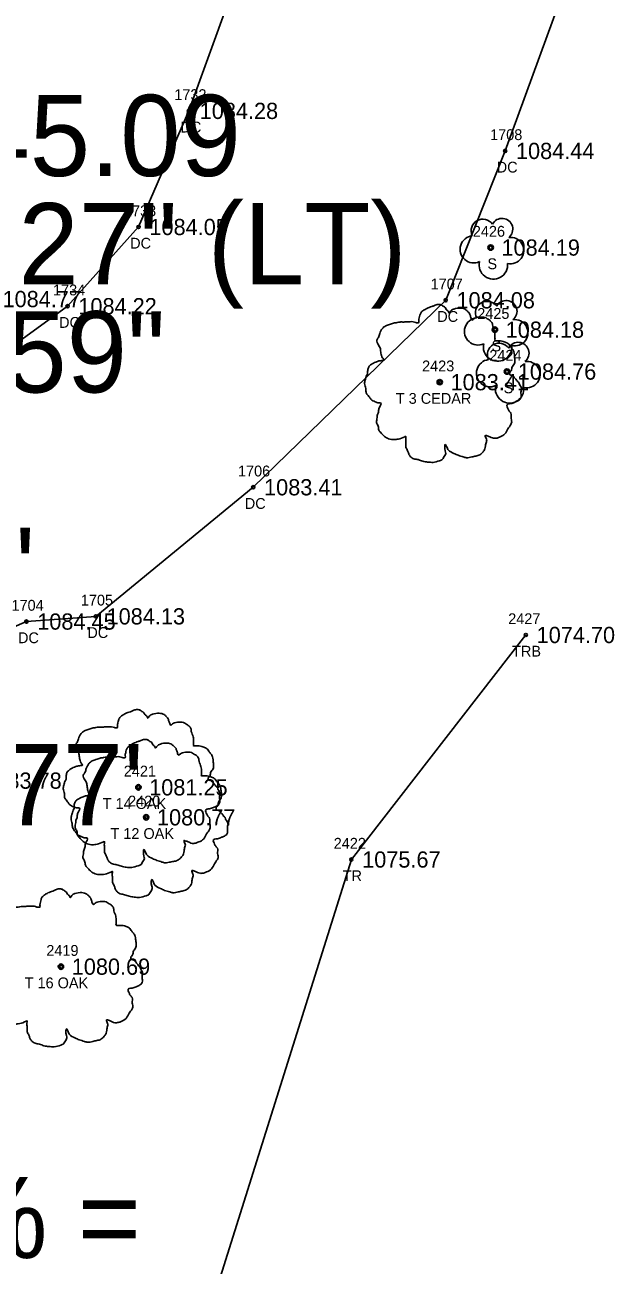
# Model space of a CAD drawing. Extents: x 1578957 to 1581675, y 1115963 to 1120391.
# Drawn here: x 1580765.6 to 1580820.1, y 1119196.4 to 1119311 of the extents above; entities that cross this region are included whole.
import ezdxf

# ---------------------------------------------------------------- set-up
doc = ezdxf.new("R2010")
doc.units = 0
for name, color, linetype in [('RD_EX_Conc', 7, 'Continuous'), ('RD_EX_Conc_txCode', 7, 'Continuous'), ('RD_EX_TX_Conc_ELEV', 7, 'Continuous'), ('RD_EX_TX_DV_Prop_ELEV', 7, 'Continuous'), ('RD_EX_TX_VEG_ELEV', 7, 'Continuous'), ('RD_EX_VEG', 7, 'Continuous'), ('RD_EX_VEG_txCode', 7, 'Continuous'), ('RD_HC_Data', 7, 'Continuous'), ('RD_SMD_Locator', 7, 'Continuous')]:
    doc.layers.add(name, color=color, linetype=linetype)

msp = doc.modelspace()

# ---------------------------------------------------------------- linework, layer by layer
at = {"layer": 'RD_EX_Conc'}
for points in [[(1580798.47, 1119328.92), (1580798.7, 1119324.38), (1580789.8, 1119327.91), (1580780.78, 1119303.02), (1580776.13, 1119292.29), (1580769.56, 1119284.97), (1580747.89, 1119269.22), (1580734.35, 1119264.63), (1580723.65, 1119263.02), (1580716.19, 1119263.31), (1580710.46, 1119268.63)], [(1580700.9, 1119243.15), (1580707.94, 1119242.34), (1580725.73, 1119233.32), (1580737.41, 1119227.45), (1580747.39, 1119244.58), (1580757.33, 1119252.19), (1580765.76, 1119255.83), (1580772.17, 1119256.31), (1580786.73, 1119268.24), (1580804.52, 1119285.52), (1580810.02, 1119299.32), (1580818.24, 1119321.88)]]:
    msp.add_lwpolyline(points, dxfattribs=at)
at = {"layer": 'RD_EX_VEG'}
msp.add_lwpolyline([(1580738.38, 1119110.04), (1580691.44, 1119109.82), (1580661.65, 1119118.46), (1580716.03, 1119209.67), (1580734.07, 1119204.79), (1580780.32, 1119184.53), (1580795.8, 1119233.84), (1580811.93, 1119254.59)], dxfattribs=at)
for centre, radius in [((1580808.68, 1119290.39), 0.25), ((1580809.07, 1119282.8), 0.25), ((1580803.97, 1119277.95), 0.25), ((1580810.19, 1119278.93), 0.25), ((1580803.96, 1119277.93), 0.0001), ((1580776.11, 1119240.51), 0.25), ((1580776.1, 1119240.49), 0.0001), ((1580776.83, 1119237.74), 0.25), ((1580776.82, 1119237.72), 0.0001), ((1580768.95, 1119223.94), 0.25), ((1580768.93, 1119223.92), 0.0001)]:
    msp.add_circle(centre, radius, dxfattribs=at)
for centre, radius, start, end in [((1580807.96, 1119291.94), 1.08, 34.9763, 204.756), ((1580809.73, 1119292.09), 0.995, 308.7626, 152.0467), ((1580807.12, 1119290.23), 1.26, 96.4518, 294.734), ((1580810.52, 1119290.11), 1.22, 256.5667, 98.1046), ((1580808.93, 1119288.79), 1.32, 166.8827, 5.7589), ((1580808.35, 1119284.34), 1.08, 34.9763, 204.756), ((1580810.12, 1119284.5), 0.995, 308.7626, 152.0467), ((1580807.51, 1119282.64), 1.26, 96.4518, 294.734), ((1580810.91, 1119282.52), 1.22, 256.5667, 98.1046), ((1580809.46, 1119280.48), 1.08, 34.9763, 204.756), ((1580811.23, 1119280.64), 0.995, 308.7626, 152.0467), ((1580809.32, 1119281.2), 1.32, 166.8827, 5.7589), ((1580808.62, 1119278.78), 1.26, 96.4518, 294.734), ((1580812.03, 1119278.65), 1.22, 256.5667, 98.1046), ((1580810.43, 1119277.34), 1.32, 166.8827, 5.7589)]:
    msp.add_arc(centre, radius, start, end, dxfattribs=at)
for points in [[(1580804.1, 1119285.11), (1580803.8, 1119285.14), (1580803.48, 1119285.04), (1580803.23, 1119284.94), (1580803, 1119284.86), (1580802.78, 1119284.76), (1580802.48, 1119284.59), (1580802.25, 1119284.39), (1580802.13, 1119284.14), (1580802.08, 1119283.91), (1580802.03, 1119283.64), (1580802.03, 1119283.46), (1580801.9, 1119283.44), (1580801.75, 1119283.46), (1580801.5, 1119283.54), (1580801.25, 1119283.54), (1580801, 1119283.54), (1580800.65, 1119283.51), (1580800.3, 1119283.51), (1580800.03, 1119283.46), (1580799.7, 1119283.41), (1580799.33, 1119283.29), (1580798.98, 1119283.16), (1580798.68, 1119282.91), (1580798.43, 1119282.44), (1580798.3, 1119282.09), (1580798.16, 1119281.84), (1580798.3, 1119281.39), (1580798.48, 1119281.04), (1580798.5, 1119280.84), (1580798.58, 1119280.41), (1580798.68, 1119280.19), (1580798.8, 1119279.99), (1580798.73, 1119279.96), (1580798.35, 1119279.91), (1580798.06, 1119279.81), (1580797.63, 1119279.59), (1580797.41, 1119279.36), (1580797.31, 1119279.04), (1580797.28, 1119278.69), (1580797.18, 1119278.49), (1580797.11, 1119278.22), (1580797.08, 1119278.14), (1580797.03, 1119277.82), (1580797.13, 1119277.37), (1580797.16, 1119277.02), (1580797.28, 1119276.79), (1580797.43, 1119276.62), (1580797.61, 1119276.37), (1580798.01, 1119276.14), (1580798.33, 1119276.04), (1580798.53, 1119276.02), (1580798.35, 1119275.52), (1580798.3, 1119275.17), (1580798.18, 1119274.77), (1580798.18, 1119274.69), (1580798.13, 1119274.22), (1580798.28, 1119273.89), (1580798.35, 1119273.52), (1580798.53, 1119273.29), (1580798.8, 1119272.99), (1580799.13, 1119272.77), (1580799.63, 1119272.64), (1580800.03, 1119272.67), (1580800.6, 1119272.84), (1580800.85, 1119272.92), (1580800.83, 1119272.74), (1580800.85, 1119272.37), (1580800.85, 1119271.94), (1580801, 1119271.62), (1580801.1, 1119271.34), (1580801.25, 1119271.09), (1580801.58, 1119270.87), (1580801.98, 1119270.79), (1580802.4, 1119270.64), (1580802.85, 1119270.57), (1580803.35, 1119270.54), (1580803.95, 1119270.69), (1580804.23, 1119270.82), (1580804.33, 1119270.99), (1580804.53, 1119271.37), (1580804.48, 1119271.59), (1580804.5, 1119272.19), (1580804.6, 1119272.02), (1580804.78, 1119271.67), (1580805.28, 1119271.37), (1580805.68, 1119271.19), (1580806.15, 1119271.04), (1580806.45, 1119270.97), (1580806.93, 1119271.04), (1580807.3, 1119271.12), (1580807.68, 1119271.24), (1580807.98, 1119271.52), (1580808.15, 1119271.79), (1580808.2, 1119272.07), (1580808.28, 1119272.44), (1580808.33, 1119272.62)], [(1580808.33, 1119272.62), (1580808.25, 1119272.79), (1580808.2, 1119273.04), (1580808.28, 1119273.02), (1580808.45, 1119272.97), (1580808.73, 1119272.84), (1580808.95, 1119272.77), (1580809.28, 1119272.79), (1580809.55, 1119272.89), (1580810, 1119273.17), (1580810.27, 1119273.64), (1580810.55, 1119274.04), (1580810.62, 1119274.37), (1580810.57, 1119274.59), (1580810.55, 1119275.09), (1580810.35, 1119275.34), (1580810.3, 1119275.47), (1580810.2, 1119275.87), (1580810.27, 1119275.92), (1580810.55, 1119275.97), (1580810.92, 1119276.09), (1580811.2, 1119276.22), (1580811.42, 1119276.39), (1580811.5, 1119276.62), (1580811.47, 1119277.02), (1580811.52, 1119277.42), (1580811.45, 1119277.57), (1580811.35, 1119277.72), (1580811.27, 1119277.92), (1580811.12, 1119278.07), (1580811.02, 1119278.22), (1580810.92, 1119278.32), (1580810.8, 1119278.47), (1580810.62, 1119278.59), (1580810.47, 1119278.64), (1580810.42, 1119278.79), (1580810.57, 1119278.99), (1580810.62, 1119279.09), (1580810.65, 1119279.31), (1580810.87, 1119279.66), (1580810.92, 1119280.06), (1580810.87, 1119280.49), (1580810.82, 1119280.76), (1580810.67, 1119281.04), (1580810.47, 1119281.29), (1580810.35, 1119281.46), (1580810.17, 1119281.59), (1580809.85, 1119281.71), (1580809.6, 1119281.76), (1580809.25, 1119281.76), (1580809.05, 1119281.81), (1580809.08, 1119281.86), (1580809.08, 1119282.01), (1580809.08, 1119282.29), (1580809, 1119282.74), (1580808.85, 1119283.24), (1580808.85, 1119283.26), (1580808.75, 1119283.51), (1580808.53, 1119283.71), (1580808.35, 1119283.81), (1580808.15, 1119283.94), (1580807.9, 1119283.96), (1580807.6, 1119283.96), (1580807.33, 1119283.91), (1580807.13, 1119283.81), (1580806.95, 1119283.69), (1580806.88, 1119283.84), (1580806.78, 1119284.14), (1580806.73, 1119284.29), (1580806.58, 1119284.46), (1580806.35, 1119284.66), (1580805.9, 1119284.79), (1580805.28, 1119284.71), (1580804.98, 1119284.51), (1580804.83, 1119284.34), (1580804.78, 1119284.46), (1580804.58, 1119284.66), (1580804.48, 1119284.84), (1580804.3, 1119284.96), (1580804.15, 1119285.06), (1580804.05, 1119285.11)], [(1580776.24, 1119247.68), (1580775.94, 1119247.7), (1580775.62, 1119247.6), (1580775.37, 1119247.5), (1580775.14, 1119247.43), (1580774.92, 1119247.33), (1580774.62, 1119247.15), (1580774.39, 1119246.95), (1580774.27, 1119246.7), (1580774.22, 1119246.48), (1580774.17, 1119246.2), (1580774.17, 1119246.03), (1580774.04, 1119246), (1580773.89, 1119246.03), (1580773.64, 1119246.1), (1580773.39, 1119246.1), (1580773.14, 1119246.1), (1580772.79, 1119246.08), (1580772.44, 1119246.08), (1580772.17, 1119246.03), (1580771.84, 1119245.98), (1580771.47, 1119245.85), (1580771.12, 1119245.73), (1580770.82, 1119245.48), (1580770.57, 1119245), (1580770.44, 1119244.65), (1580770.29, 1119244.4), (1580770.44, 1119243.95), (1580770.62, 1119243.6), (1580770.64, 1119243.4), (1580770.72, 1119242.98), (1580770.82, 1119242.75), (1580770.94, 1119242.55), (1580770.87, 1119242.53), (1580770.49, 1119242.48), (1580770.19, 1119242.38), (1580769.77, 1119242.15), (1580769.54, 1119241.93), (1580769.44, 1119241.6), (1580769.42, 1119241.25), (1580769.32, 1119241.05), (1580769.24, 1119240.78), (1580769.22, 1119240.7), (1580769.17, 1119240.38), (1580769.27, 1119239.93), (1580769.29, 1119239.58), (1580769.42, 1119239.36), (1580769.57, 1119239.18), (1580769.74, 1119238.93), (1580770.14, 1119238.71), (1580770.47, 1119238.61), (1580770.67, 1119238.58), (1580770.49, 1119238.08), (1580770.44, 1119237.73), (1580770.32, 1119237.33), (1580770.32, 1119237.26), (1580770.27, 1119236.78), (1580770.42, 1119236.46), (1580770.49, 1119236.08), (1580770.67, 1119235.86), (1580770.94, 1119235.56), (1580771.27, 1119235.33), (1580771.77, 1119235.21), (1580772.17, 1119235.23), (1580772.74, 1119235.41), (1580772.99, 1119235.48), (1580772.97, 1119235.31), (1580772.99, 1119234.93), (1580772.99, 1119234.51), (1580773.14, 1119234.18), (1580773.24, 1119233.91), (1580773.39, 1119233.66), (1580773.72, 1119233.43), (1580774.12, 1119233.36), (1580774.54, 1119233.21), (1580774.99, 1119233.13), (1580775.49, 1119233.11), (1580776.09, 1119233.26), (1580776.37, 1119233.38), (1580776.47, 1119233.56), (1580776.67, 1119233.93), (1580776.62, 1119234.16), (1580776.64, 1119234.76), (1580776.74, 1119234.58), (1580776.92, 1119234.23), (1580777.42, 1119233.93), (1580777.82, 1119233.76), (1580778.29, 1119233.61), (1580778.59, 1119233.53), (1580779.06, 1119233.61), (1580779.44, 1119233.68), (1580779.81, 1119233.81), (1580780.11, 1119234.08), (1580780.29, 1119234.36), (1580780.34, 1119234.63), (1580780.41, 1119235.01), (1580780.46, 1119235.18)], [(1580780.46, 1119235.18), (1580780.39, 1119235.36), (1580780.34, 1119235.61), (1580780.41, 1119235.58), (1580780.59, 1119235.53), (1580780.86, 1119235.41), (1580781.09, 1119235.33), (1580781.41, 1119235.36), (1580781.69, 1119235.46), (1580782.14, 1119235.73), (1580782.41, 1119236.21), (1580782.69, 1119236.61), (1580782.76, 1119236.93), (1580782.71, 1119237.16), (1580782.69, 1119237.66), (1580782.49, 1119237.91), (1580782.44, 1119238.03), (1580782.34, 1119238.43), (1580782.41, 1119238.48), (1580782.69, 1119238.53), (1580783.06, 1119238.66), (1580783.34, 1119238.78), (1580783.56, 1119238.96), (1580783.64, 1119239.18), (1580783.61, 1119239.58), (1580783.66, 1119239.98), (1580783.59, 1119240.13), (1580783.49, 1119240.28), (1580783.41, 1119240.48), (1580783.26, 1119240.63), (1580783.16, 1119240.78), (1580783.06, 1119240.88), (1580782.94, 1119241.03), (1580782.76, 1119241.15), (1580782.61, 1119241.2), (1580782.56, 1119241.35), (1580782.71, 1119241.55), (1580782.76, 1119241.65), (1580782.79, 1119241.88), (1580783.01, 1119242.23), (1580783.06, 1119242.63), (1580783.01, 1119243.05), (1580782.96, 1119243.33), (1580782.81, 1119243.6), (1580782.61, 1119243.85), (1580782.49, 1119244.03), (1580782.31, 1119244.15), (1580781.99, 1119244.28), (1580781.74, 1119244.33), (1580781.39, 1119244.33), (1580781.19, 1119244.38), (1580781.21, 1119244.43), (1580781.21, 1119244.58), (1580781.21, 1119244.85), (1580781.14, 1119245.3), (1580780.99, 1119245.8), (1580780.99, 1119245.83), (1580780.89, 1119246.08), (1580780.66, 1119246.28), (1580780.49, 1119246.38), (1580780.29, 1119246.5), (1580780.04, 1119246.53), (1580779.74, 1119246.53), (1580779.46, 1119246.48), (1580779.26, 1119246.38), (1580779.09, 1119246.25), (1580779.01, 1119246.4), (1580778.91, 1119246.7), (1580778.86, 1119246.85), (1580778.71, 1119247.03), (1580778.49, 1119247.23), (1580778.04, 1119247.35), (1580777.42, 1119247.28), (1580777.12, 1119247.08), (1580776.97, 1119246.9), (1580776.92, 1119247.03), (1580776.72, 1119247.23), (1580776.62, 1119247.4), (1580776.44, 1119247.53), (1580776.29, 1119247.63), (1580776.19, 1119247.68)], [(1580776.97, 1119244.91), (1580776.67, 1119244.94), (1580776.34, 1119244.84), (1580776.09, 1119244.74), (1580775.87, 1119244.66), (1580775.64, 1119244.56), (1580775.34, 1119244.39), (1580775.12, 1119244.19), (1580774.99, 1119243.94), (1580774.94, 1119243.71), (1580774.89, 1119243.44), (1580774.89, 1119243.26), (1580774.77, 1119243.24), (1580774.62, 1119243.26), (1580774.37, 1119243.34), (1580774.12, 1119243.34), (1580773.87, 1119243.34), (1580773.52, 1119243.31), (1580773.17, 1119243.31), (1580772.89, 1119243.26), (1580772.57, 1119243.21), (1580772.19, 1119243.09), (1580771.84, 1119242.96), (1580771.54, 1119242.71), (1580771.29, 1119242.24), (1580771.17, 1119241.89), (1580771.02, 1119241.64), (1580771.17, 1119241.19), (1580771.34, 1119240.84), (1580771.37, 1119240.64), (1580771.44, 1119240.21), (1580771.54, 1119239.99), (1580771.67, 1119239.79), (1580771.59, 1119239.76), (1580771.22, 1119239.71), (1580770.92, 1119239.61), (1580770.49, 1119239.39), (1580770.27, 1119239.16), (1580770.17, 1119238.84), (1580770.14, 1119238.49), (1580770.04, 1119238.29), (1580769.97, 1119238.01), (1580769.94, 1119237.94), (1580769.89, 1119237.61), (1580769.99, 1119237.16), (1580770.02, 1119236.81), (1580770.14, 1119236.59), (1580770.29, 1119236.41), (1580770.47, 1119236.16), (1580770.87, 1119235.94), (1580771.19, 1119235.84), (1580771.39, 1119235.81), (1580771.22, 1119235.31), (1580771.17, 1119234.96), (1580771.04, 1119234.57), (1580771.04, 1119234.49), (1580770.99, 1119234.02), (1580771.14, 1119233.69), (1580771.22, 1119233.32), (1580771.39, 1119233.09), (1580771.67, 1119232.79), (1580771.99, 1119232.57), (1580772.49, 1119232.44), (1580772.89, 1119232.47), (1580773.47, 1119232.64), (1580773.72, 1119232.72), (1580773.69, 1119232.54), (1580773.72, 1119232.17), (1580773.72, 1119231.74), (1580773.87, 1119231.42), (1580773.97, 1119231.14), (1580774.12, 1119230.89), (1580774.44, 1119230.67), (1580774.84, 1119230.59), (1580775.27, 1119230.44), (1580775.72, 1119230.37), (1580776.22, 1119230.34), (1580776.82, 1119230.49), (1580777.09, 1119230.62), (1580777.19, 1119230.79), (1580777.39, 1119231.17), (1580777.34, 1119231.39), (1580777.37, 1119231.99), (1580777.47, 1119231.82), (1580777.64, 1119231.47), (1580778.14, 1119231.17), (1580778.54, 1119230.99), (1580779.01, 1119230.84), (1580779.31, 1119230.77), (1580779.79, 1119230.84), (1580780.16, 1119230.92), (1580780.54, 1119231.04), (1580780.84, 1119231.32), (1580781.01, 1119231.59), (1580781.06, 1119231.87), (1580781.14, 1119232.24), (1580781.19, 1119232.42)], [(1580781.19, 1119232.42), (1580781.11, 1119232.59), (1580781.06, 1119232.84), (1580781.14, 1119232.82), (1580781.31, 1119232.77), (1580781.59, 1119232.64), (1580781.81, 1119232.57), (1580782.14, 1119232.59), (1580782.41, 1119232.69), (1580782.86, 1119232.97), (1580783.14, 1119233.44), (1580783.41, 1119233.84), (1580783.49, 1119234.17), (1580783.44, 1119234.39), (1580783.41, 1119234.89), (1580783.21, 1119235.14), (1580783.16, 1119235.26), (1580783.06, 1119235.66), (1580783.14, 1119235.71), (1580783.41, 1119235.76), (1580783.79, 1119235.89), (1580784.06, 1119236.01), (1580784.29, 1119236.19), (1580784.36, 1119236.41), (1580784.34, 1119236.81), (1580784.39, 1119237.21), (1580784.31, 1119237.36), (1580784.21, 1119237.51), (1580784.14, 1119237.71), (1580783.99, 1119237.86), (1580783.89, 1119238.01), (1580783.79, 1119238.11), (1580783.66, 1119238.26), (1580783.49, 1119238.39), (1580783.34, 1119238.44), (1580783.29, 1119238.59), (1580783.44, 1119238.79), (1580783.49, 1119238.89), (1580783.51, 1119239.11), (1580783.74, 1119239.46), (1580783.79, 1119239.86), (1580783.74, 1119240.29), (1580783.69, 1119240.56), (1580783.54, 1119240.84), (1580783.34, 1119241.09), (1580783.21, 1119241.26), (1580783.04, 1119241.39), (1580782.71, 1119241.51), (1580782.46, 1119241.56), (1580782.11, 1119241.56), (1580781.91, 1119241.61), (1580781.94, 1119241.66), (1580781.94, 1119241.81), (1580781.94, 1119242.09), (1580781.86, 1119242.54), (1580781.71, 1119243.04), (1580781.71, 1119243.06), (1580781.61, 1119243.31), (1580781.39, 1119243.51), (1580781.21, 1119243.61), (1580781.01, 1119243.74), (1580780.76, 1119243.76), (1580780.46, 1119243.76), (1580780.19, 1119243.71), (1580779.99, 1119243.61), (1580779.81, 1119243.49), (1580779.74, 1119243.64), (1580779.64, 1119243.94), (1580779.59, 1119244.09), (1580779.44, 1119244.26), (1580779.21, 1119244.46), (1580778.76, 1119244.59), (1580778.14, 1119244.51), (1580777.84, 1119244.31), (1580777.69, 1119244.14), (1580777.64, 1119244.26), (1580777.44, 1119244.46), (1580777.34, 1119244.64), (1580777.17, 1119244.76), (1580777.02, 1119244.86), (1580776.92, 1119244.91)], [(1580769.08, 1119231.1), (1580768.78, 1119231.13), (1580768.45, 1119231.03), (1580768.2, 1119230.93), (1580767.98, 1119230.85), (1580767.75, 1119230.75), (1580767.45, 1119230.58), (1580767.23, 1119230.38), (1580767.11, 1119230.13), (1580767.06, 1119229.9), (1580767.01, 1119229.63), (1580767.01, 1119229.45), (1580766.88, 1119229.43), (1580766.73, 1119229.45), (1580766.48, 1119229.53), (1580766.23, 1119229.53), (1580765.98, 1119229.53), (1580765.63, 1119229.5), (1580765.28, 1119229.5), (1580765.01, 1119229.45), (1580764.68, 1119229.4), (1580764.31, 1119229.28), (1580763.96, 1119229.15), (1580763.66, 1119228.9), (1580763.41, 1119228.43), (1580763.28, 1119228.08), (1580763.13, 1119227.83), (1580763.28, 1119227.38), (1580763.46, 1119227.03), (1580763.48, 1119226.83), (1580763.56, 1119226.4), (1580763.66, 1119226.18), (1580763.78, 1119225.98), (1580763.71, 1119225.95), (1580763.33, 1119225.9), (1580763.03, 1119225.8), (1580762.61, 1119225.58), (1580762.38, 1119225.35), (1580762.28, 1119225.03), (1580762.26, 1119224.68), (1580762.16, 1119224.48), (1580762.08, 1119224.21), (1580762.06, 1119224.13), (1580762.01, 1119223.81), (1580762.11, 1119223.36), (1580762.13, 1119223.01), (1580762.26, 1119222.78), (1580762.41, 1119222.61), (1580762.58, 1119222.36), (1580762.98, 1119222.13), (1580763.31, 1119222.03), (1580763.51, 1119222.01), (1580763.33, 1119221.51), (1580763.28, 1119221.16), (1580763.16, 1119220.76), (1580763.16, 1119220.68), (1580763.11, 1119220.21), (1580763.26, 1119219.88), (1580763.33, 1119219.51), (1580763.51, 1119219.28), (1580763.78, 1119218.98), (1580764.11, 1119218.76), (1580764.61, 1119218.63), (1580765.01, 1119218.66), (1580765.58, 1119218.83), (1580765.83, 1119218.91), (1580765.81, 1119218.73), (1580765.83, 1119218.36), (1580765.83, 1119217.93), (1580765.98, 1119217.61), (1580766.08, 1119217.33), (1580766.23, 1119217.08), (1580766.56, 1119216.86), (1580766.96, 1119216.78), (1580767.38, 1119216.63), (1580767.83, 1119216.56), (1580768.33, 1119216.53), (1580768.93, 1119216.68), (1580769.2, 1119216.81), (1580769.3, 1119216.98), (1580769.5, 1119217.36), (1580769.45, 1119217.58), (1580769.48, 1119218.18), (1580769.58, 1119218.01), (1580769.75, 1119217.66), (1580770.25, 1119217.36), (1580770.65, 1119217.18), (1580771.13, 1119217.03), (1580771.43, 1119216.96), (1580771.9, 1119217.03), (1580772.28, 1119217.11), (1580772.65, 1119217.23), (1580772.95, 1119217.51), (1580773.13, 1119217.78), (1580773.18, 1119218.06), (1580773.25, 1119218.43), (1580773.3, 1119218.61)], [(1580773.3, 1119218.61), (1580773.23, 1119218.78), (1580773.18, 1119219.03), (1580773.25, 1119219.01), (1580773.43, 1119218.96), (1580773.7, 1119218.83), (1580773.93, 1119218.76), (1580774.25, 1119218.78), (1580774.53, 1119218.88), (1580774.98, 1119219.16), (1580775.25, 1119219.63), (1580775.53, 1119220.03), (1580775.6, 1119220.36), (1580775.55, 1119220.58), (1580775.53, 1119221.08), (1580775.33, 1119221.33), (1580775.28, 1119221.46), (1580775.18, 1119221.86), (1580775.25, 1119221.91), (1580775.53, 1119221.96), (1580775.9, 1119222.08), (1580776.18, 1119222.21), (1580776.4, 1119222.38), (1580776.48, 1119222.61), (1580776.45, 1119223.01), (1580776.5, 1119223.41), (1580776.43, 1119223.56), (1580776.33, 1119223.71), (1580776.25, 1119223.91), (1580776.1, 1119224.06), (1580776, 1119224.21), (1580775.9, 1119224.31), (1580775.78, 1119224.46), (1580775.6, 1119224.58), (1580775.45, 1119224.63), (1580775.4, 1119224.78), (1580775.55, 1119224.98), (1580775.6, 1119225.08), (1580775.63, 1119225.3), (1580775.85, 1119225.65), (1580775.9, 1119226.05), (1580775.85, 1119226.48), (1580775.8, 1119226.75), (1580775.65, 1119227.03), (1580775.45, 1119227.28), (1580775.33, 1119227.45), (1580775.15, 1119227.58), (1580774.83, 1119227.7), (1580774.58, 1119227.75), (1580774.23, 1119227.75), (1580774.03, 1119227.8), (1580774.05, 1119227.85), (1580774.05, 1119228), (1580774.05, 1119228.28), (1580773.98, 1119228.73), (1580773.83, 1119229.23), (1580773.83, 1119229.25), (1580773.73, 1119229.5), (1580773.5, 1119229.7), (1580773.33, 1119229.8), (1580773.13, 1119229.93), (1580772.88, 1119229.95), (1580772.58, 1119229.95), (1580772.3, 1119229.9), (1580772.1, 1119229.8), (1580771.93, 1119229.68), (1580771.85, 1119229.83), (1580771.75, 1119230.13), (1580771.7, 1119230.28), (1580771.55, 1119230.45), (1580771.33, 1119230.65), (1580770.88, 1119230.78), (1580770.25, 1119230.7), (1580769.95, 1119230.5), (1580769.8, 1119230.33), (1580769.75, 1119230.45), (1580769.55, 1119230.65), (1580769.45, 1119230.83), (1580769.28, 1119230.95), (1580769.13, 1119231.05), (1580769.03, 1119231.1)]]:
    msp.add_spline(points, degree=3, dxfattribs=at)
at = {"layer": 'RD_SMD_Locator'}
for centre in [(1580780.78, 1119303.02), (1580810.02, 1119299.32), (1580776.13, 1119292.29), (1580808.68, 1119290.39), (1580769.56, 1119284.97), (1580804.52, 1119285.52), (1580809.07, 1119282.8), (1580803.97, 1119277.95), (1580810.19, 1119278.93), (1580786.73, 1119268.24), (1580772.17, 1119256.31), (1580765.76, 1119255.83), (1580811.93, 1119254.59), (1580776.11, 1119240.51), (1580776.83, 1119237.74), (1580795.8, 1119233.84), (1580768.95, 1119223.94)]:
    msp.add_circle(centre, 0.15, dxfattribs=at)

# ---------------------------------------------------------------- texts
at = {"layer": 'RD_EX_Conc_txCode'}
for s, p in [('1732', (1580779.43, 1119304.02)), ('DC', (1580780, 1119301.02)), ('1708', (1580808.63, 1119300.32)), ('DC', (1580809.24, 1119297.32)), ('1733', (1580774.78, 1119293.29)), ('DC', (1580775.35, 1119290.29)), ('1707', (1580803.13, 1119286.52)), ('1734', (1580768.22, 1119285.97)), ('DC', (1580768.78, 1119282.97)), ('DC', (1580803.74, 1119283.52)), ('1706', (1580785.32, 1119269.24)), ('DC', (1580785.95, 1119266.24)), ('1704', (1580764.38, 1119256.83)), ('1705', (1580770.79, 1119257.31)), ('DC', (1580771.39, 1119254.31)), ('DC', (1580764.98, 1119253.83))]:
    msp.add_text(s, height=1, dxfattribs=at).set_placement(p)
at = {"layer": 'RD_EX_TX_Conc_ELEV'}
for s, p in [('1084.28', (1580781.78, 1119302.27)), ('1084.44', (1580811.02, 1119298.57)), ('1084.05', (1580777.13, 1119291.54)), ('1084.08', (1580805.52, 1119284.77)), ('1084.22', (1580770.56, 1119284.22)), ('1083.41', (1580787.73, 1119267.49)), ('1084.45', (1580766.76, 1119255.08)), ('1084.13', (1580773.17, 1119255.56))]:
    msp.add_text(s, height=1.5, dxfattribs=at).set_placement(p)
at = {"layer": 'RD_EX_TX_DV_Prop_ELEV'}
msp.add_text('1083.78', height=1.5, dxfattribs=at).set_placement((1580761.77, 1119240.38))
at = {"layer": 'RD_EX_TX_VEG_ELEV'}
for s, p in [('1084.19', (1580809.68, 1119289.64)), ('1084.77', (1580763.55, 1119284.88)), ('1084.18', (1580810.07, 1119282.05)), ('1084.76', (1580811.19, 1119278.18)), ('1083.41', (1580804.97, 1119277.2)), ('1074.70', (1580812.93, 1119253.84)), ('1081.25', (1580777.11, 1119239.76)), ('1080.77', (1580777.83, 1119236.99)), ('1075.67', (1580796.8, 1119233.09)), ('1080.69', (1580769.95, 1119223.19))]:
    msp.add_text(s, height=1.5, dxfattribs=at).set_placement(p)
at = {"layer": 'RD_EX_VEG_txCode'}
for s, p in [('2426', (1580807.03, 1119291.39)), ('S', (1580808.38, 1119288.39)), ('2425', (1580807.44, 1119283.8)), ('S', (1580808.76, 1119280.8)), ('2424', (1580808.56, 1119279.93)), ('2423', (1580802.34, 1119278.95)), ('T 3 CEDAR', (1580799.91, 1119275.95)), ('S', (1580809.88, 1119276.93)), ('2427', (1580810.3, 1119255.59)), ('TRB', (1580810.66, 1119252.59)), ('2421', (1580774.76, 1119241.51)), ('T 14 OAK', (1580772.81, 1119238.51)), ('2420', (1580775.16, 1119238.74)), ('T 12 OAK', (1580773.53, 1119235.74)), ('2422', (1580794.17, 1119234.84)), ('TR', (1580795, 1119231.84)), ('2419', (1580767.6, 1119224.94)), ('T 16 OAK', (1580765.6, 1119221.94))]:
    msp.add_text(s, height=1, dxfattribs=at).set_placement(p)
at = {"layer": 'RD_HC_Data'}
for s, p in [('P.I. = 41+45.09', (1580717, 1119297)), ('    = 2%%d 55\' 27" (LT)', (1580717, 1119287)), ('D = 2%%d 14\' 59"', (1580717, 1119277)), ("L = 129.97'", (1580717, 1119257)), ("R = 2,546.77'", (1580717, 1119237)), ('P.C. - LG% = ', (1580717, 1119197))]:
    msp.add_text(s, height=7.5, dxfattribs=at).set_placement(p)

doc.saveas('drawing.dxf')
